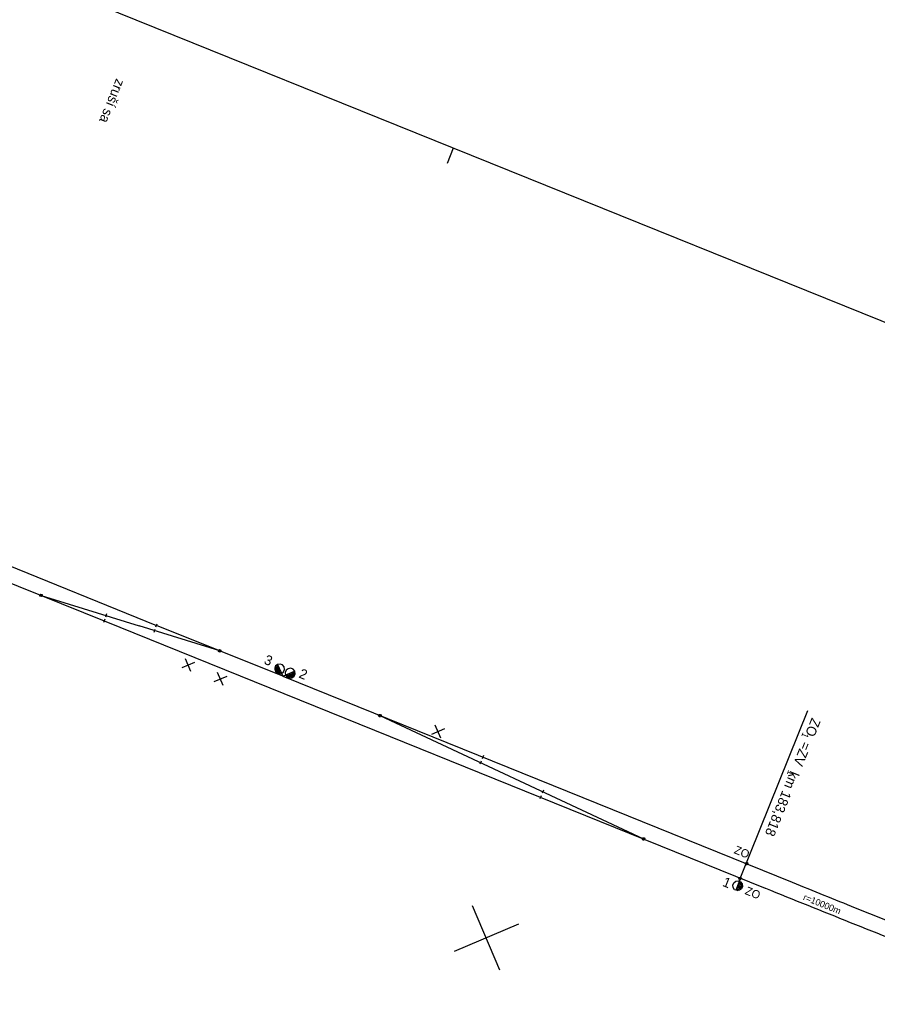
# Model space of a CAD drawing. Extents: x -467542 to -465211, y -1328177 to -1327037.
# Drawn here: x -466005.7 to -465743.4, y -1327925.3 to -1327626.7 of the extents above; entities that cross this region are included whole.
import ezdxf

# ---------------------------------------------------------------- set-up
doc = ezdxf.new("R2010")
doc.units = 0
for name, color, linetype in [('Level 1', 7, 'Continuous'), ('Level 10', 7, 'Continuous'), ('Level 11', 7, 'Continuous'), ('Level 6', 7, 'Continuous'), ('Level 61', 7, 'Continuous')]:
    doc.layers.add(name, color=color, linetype=linetype)

msp = doc.modelspace()

# ---------------------------------------------------------------- linework, layer by layer
at = {"layer": 'Level 1'}
for p, q in [((-466030.58, -1327785.05), (-465963.83, -1327812.05)), ((-466018.46, -1327795.08), (-465979.9, -1327810.67)), ((-465999.18, -1327802.88), (-465999.18, -1327802.88)), ((-465999.18, -1327802.88), (-465969.19, -1327812.19)), ((-465979.71, -1327810.21), (-465980.08, -1327811.14)), ((-465979.9, -1327810.67), (-465777.7, -1327892.45)), ((-465979.9, -1327810.67), (-465979.9, -1327810.67)), ((-465979.17, -1327808.57), (-465979.46, -1327809.52)), ((-465979.32, -1327809.05), (-465979.32, -1327809.05)), ((-465944.55, -1327819.85), (-465969.19, -1327812.19)), ((-465964.56, -1327814.15), (-465964.26, -1327813.2)), ((-465964.41, -1327813.68), (-465964.41, -1327813.68)), ((-465964.02, -1327812.51), (-465963.64, -1327811.58)), ((-465925.27, -1327827.64), (-465963.83, -1327812.05)), ((-465963.83, -1327812.05), (-465963.83, -1327812.05)), ((-465944.55, -1327819.85), (-465944.55, -1327819.85)), ((-465925.27, -1327827.64), (-465769.46, -1327890.66)), ((-465895.58, -1327839.65), (-465895.58, -1327839.65)), ((-465895.58, -1327839.65), (-465814.93, -1327877.4)), ((-465863.87, -1327851.92), (-465864.24, -1327852.85)), ((-465864.06, -1327852.38), (-465864.06, -1327852.38)), ((-465864.63, -1327853.6), (-465865, -1327854.53)), ((-465864.81, -1327854.06), (-465864.81, -1327854.06)), ((-465846.25, -1327864.19), (-465846.63, -1327865.12)), ((-465845.52, -1327862.51), (-465845.9, -1327863.44)), ((-465845.71, -1327862.98), (-465845.71, -1327862.98)), ((-465846.44, -1327864.66), (-465846.44, -1327864.66)), ((-465814.93, -1327877.4), (-465814.93, -1327877.4)), ((-465783.45, -1327884.95), (-465783.45, -1327884.95)), ((-465785.4, -1327889.49), (-465785.4, -1327889.49)), ((-465750.21, -1327898.43), (-465683.62, -1327925.29))]:
    msp.add_line(p, q, dxfattribs=at)
for points in [[(-465998.81, -1327803.03), (-465999.12, -1327803.27), (-465999.49, -1327803.12), (-465999.55, -1327802.73), (-465999.23, -1327802.48), (-465998.86, -1327802.63), (-465998.81, -1327803.03)], [(-465944.92, -1327819.7), (-465944.61, -1327819.45), (-465944.24, -1327819.6), (-465944.18, -1327820), (-465944.5, -1327820.24), (-465944.87, -1327820.09), (-465944.92, -1327819.7)], [(-465895.18, -1327839.65), (-465895.38, -1327840), (-465895.78, -1327840), (-465895.98, -1327839.65), (-465895.78, -1327839.3), (-465895.38, -1327839.3), (-465895.18, -1327839.65)], [(-465814.53, -1327877.4), (-465814.73, -1327877.74), (-465815.13, -1327877.74), (-465815.33, -1327877.4), (-465815.13, -1327877.05), (-465814.73, -1327877.05), (-465814.53, -1327877.4)], [(-465783.6, -1327885.32), (-465783.84, -1327885.01), (-465783.69, -1327884.64), (-465783.29, -1327884.58), (-465783.05, -1327884.9), (-465783.2, -1327885.27), (-465783.6, -1327885.32)], [(-465785.55, -1327889.86), (-465785.8, -1327889.55), (-465785.65, -1327889.18), (-465785.25, -1327889.12), (-465785.01, -1327889.44), (-465785.15, -1327889.81), (-465785.55, -1327889.86)]]:
    msp.add_lwpolyline(points, dxfattribs=at)
for centre, radius, start, end in [((-458270.21, -1309349.86), 20000, 247.978006, 248.037461), ((-462028.55, -1318621.86), 10000, 247.980981, 248.301869)]:
    msp.add_arc(centre, radius, start, end, dxfattribs=at)
at = {"layer": 'Level 11'}
for p, q in [((-465953.36, -1327826.19), (-465955.03, -1327822.26)), ((-465952.23, -1327823.39), (-465956.17, -1327825.06)), ((-465942.37, -1327827.66), (-465946.3, -1327829.33)), ((-465943.5, -1327830.46), (-465945.17, -1327826.52)), ((-465925.27, -1327827.64), (-465925.27, -1327827.64)), ((-465764.77, -1327838.2), (-465785.33, -1327889.09)), ((-465876.96, -1327846.55), (-465878.63, -1327842.62)), ((-465875.82, -1327843.75), (-465879.76, -1327845.42)), ((-465785.24, -1327889.4), (-465786.72, -1327893.06)), ((-465785.24, -1327889.4), (-465785.24, -1327889.4)), ((-465858.87, -1327917.54), (-465867.22, -1327897.86)), ((-465853.21, -1327903.52), (-465872.88, -1327911.87))]:
    msp.add_line(p, q, dxfattribs=at)
for points in [[(-465925.65, -1327826.75), (-465925.04, -1327826.27), (-465924.75, -1327825.55), (-465924.86, -1327824.78), (-465925.34, -1327824.17), (-465926.06, -1327823.88), (-465926.83, -1327823.99), (-465927.44, -1327824.46), (-465927.73, -1327825.18), (-465927.62, -1327825.95), (-465927.15, -1327826.56), (-465926.42, -1327826.85), (-465925.65, -1327826.75), (-465925.93, -1327826.46), (-465926.51, -1327826.71), (-465926.88, -1327826.56), (-465926.1, -1327826.23), (-465926.2, -1327825.92), (-465927.12, -1327826.36), (-465927.35, -1327826.1), (-465926.3, -1327825.66), (-465926.42, -1327825.4), (-465927.5, -1327825.83), (-465927.55, -1327825.54), (-465926.51, -1327825.1), (-465926.62, -1327824.83), (-465927.53, -1327825.22), (-465927.43, -1327824.83), (-465926.78, -1327824.56), (-465926.87, -1327824.25), (-465927.19, -1327824.39)], [(-465926.82, -1327824), (-465925.27, -1327827.64), (-465921.63, -1327826.1)], [(-465921.61, -1327826.09), (-465922.09, -1327825.48), (-465922.81, -1327825.19), (-465923.62, -1327825.31), (-465924.19, -1327825.77), (-465924.48, -1327826.49), (-465924.38, -1327827.26), (-465923.9, -1327827.88), (-465923.18, -1327828.17), (-465922.45, -1327828.07), (-465921.8, -1327827.58), (-465921.51, -1327826.86), (-465921.61, -1327826.09), (-465921.85, -1327826.38), (-465921.66, -1327826.84), (-465921.83, -1327827.26), (-465922.13, -1327826.54), (-465922.39, -1327826.65), (-465922, -1327827.56), (-465922.26, -1327827.78), (-465922.7, -1327826.74), (-465922.98, -1327826.9), (-465922.52, -1327827.9), (-465922.82, -1327827.99), (-465923.24, -1327827.01), (-465923.5, -1327827.12), (-465923.11, -1327828.03), (-465923.53, -1327827.86), (-465923.8, -1327827.21), (-465924.06, -1327827.32), (-465923.9, -1327827.71)], [(-465786.35, -1327893.22), (-465787.09, -1327892.92), (-465787.57, -1327892.28), (-465787.67, -1327891.55), (-465787.37, -1327890.81), (-465786.76, -1327890.34), (-465786.01, -1327890.23), (-465785.26, -1327890.53), (-465784.8, -1327891.14), (-465784.69, -1327891.9), (-465784.98, -1327892.62), (-465785.59, -1327893.1), (-465786.35, -1327893.22), (-465786.02, -1327893.08), (-465786.49, -1327892.89), (-465786.38, -1327892.61), (-465785.59, -1327892.93), (-465785.34, -1327892.71), (-465786.26, -1327892.33), (-465786.15, -1327892.05), (-465785.09, -1327892.49), (-465784.97, -1327892.21), (-465786.04, -1327891.78), (-465785.93, -1327891.5), (-465784.86, -1327891.93), (-465784.89, -1327891.59), (-465785.81, -1327891.22), (-465785.7, -1327890.94), (-465784.96, -1327891.24), (-465785.17, -1327890.83), (-465785.59, -1327890.67)]]:
    msp.add_lwpolyline(points, dxfattribs=at)
at = {"layer": 'Level 61'}
for p, q in [((-466651.85, -1327351.35), (-465288.89, -1327902.03)), ((-465874.89, -1327670.66), (-465873.01, -1327666.02))]:
    msp.add_line(p, q, dxfattribs=at)

# ---------------------------------------------------------------- texts
at = {"layer": 'Level 10'}
msp.add_text('r=10000m', height=2, rotation=338, dxfattribs=at).set_placement((-465766.32, -1327895.96))
at = {"layer": 'Level 11'}
for s, height, rotation, p in [('3', 3, 338, (-465931.22, -1327823.72)), ('2', 3, 338, (-465920.56, -1327827.95)), ('ZO  =ZV  km 183,818', 3, 248, (-465763.47, -1327840.16)), ('1', 2, 248, (-465766.17, -1327844.64)), ('1', 2, 248, (-465770.59, -1327856.19)), ('ZO', 2.5, 338, (-465787.48, -1327881.69)), ('1', 3, 338, (-465791.04, -1327891.7)), ('ZO', 2.5, 338, (-465784.14, -1327894.19))]:
    msp.add_text(s, height=height, rotation=rotation, dxfattribs=at).set_placement(p)
at = {"layer": 'Level 6'}
msp.add_text('zruší sa', height=3, rotation=248, dxfattribs=at).set_placement((-465976.16, -1327644.61))

doc.saveas('drawing.dxf')
